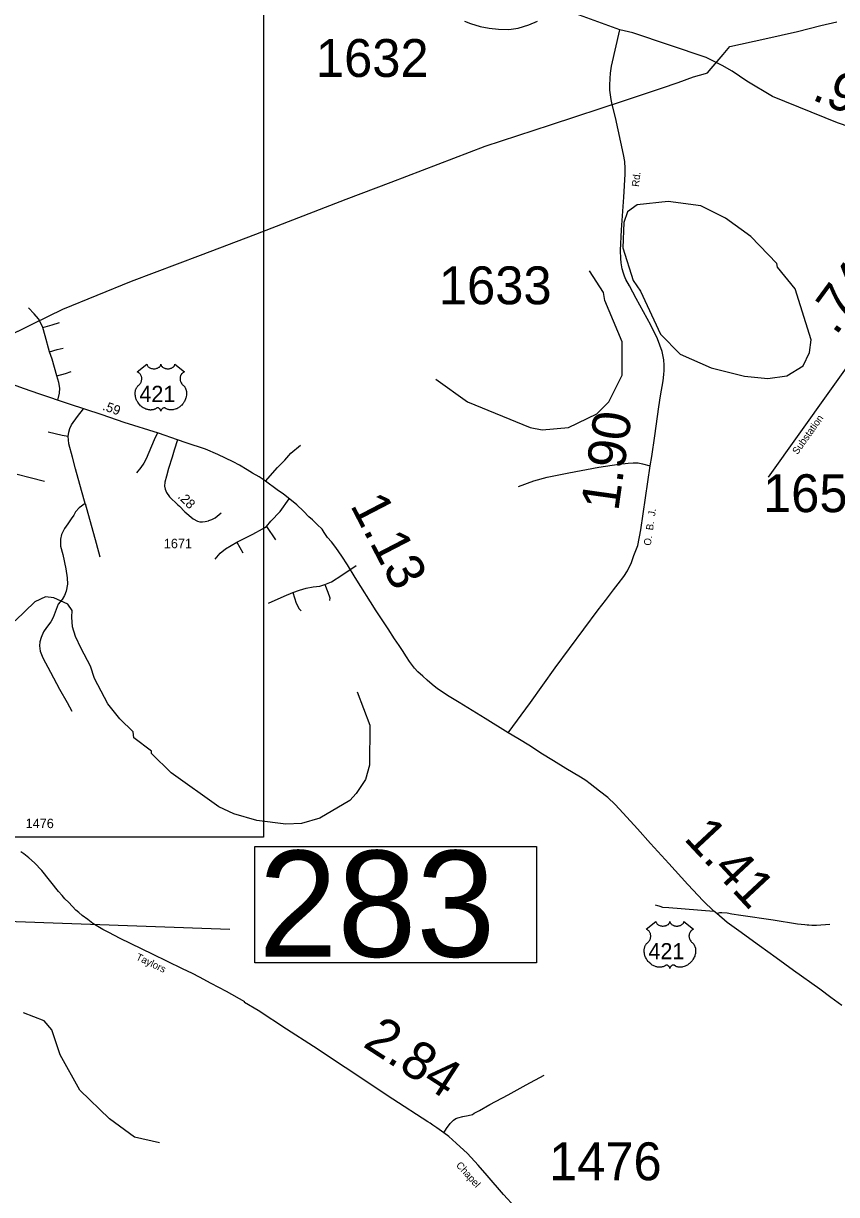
# Model space of a CAD drawing. Extents: x 2093524 to 2270757, y 289120 to 570408.
# Drawn here: x 2138622 to 2149355, y 529637 to 545096 of the extents above; entities that cross this region are included whole.
import ezdxf

# ---------------------------------------------------------------- set-up
doc = ezdxf.new("R2010")
doc.units = 0
for name, color, linetype in [('Exist Hydrographic Creek Single Shore', 7, 'Continuous'), ('Exist Hydrographic Misc Water Feature', 7, 'Continuous'), ('Exist Hydrographic Pond Under 1500 Sq Ft', 7, 'Continuous'), ('Exist Road Non-System Type 51', 7, 'Continuous'), ('Exist Road Primary US Attributed', 7, 'Continuous'), ('Exist Road Primary US Mileage Hundredths English Label', 7, 'Continuous'), ('Exist Road Primary US Shield CELL', 7, 'Continuous'), ('Exist Road Primary US Shield Number Label', 7, 'Continuous'), ('Exist Road Secondary Mileage Hundredths English Label', 7, 'Continuous'), ('Exist Road Secondary Structure Standard Bridge Number Label', 7, 'Continuous'), ('Exist Road Secondary Type 51 Attributed', 7, 'Continuous'), ('Exist Road Secondary Type 51 Label', 7, 'Continuous'), ('Exist Road Secondary Type 51 Number Label', 7, 'Continuous'), ('Exist Utilities Electrical Transmission Line', 7, 'Continuous'), ('Map Preparation Inset Cut Line', 7, 'Continuous')]:
    doc.layers.add(name, color=color, linetype=linetype)

msp = doc.modelspace()

# ---------------------------------------------------------------- linework, layer by layer
at = {"layer": 'Exist Hydrographic Creek Single Shore'}
for points in [[(2143026, 536271), (2143195, 535831), (2143188, 535306), (2143139, 535114), (2143016, 534929), (2142932, 534839), (2142533, 534605), (2142293, 534534), (2142084, 534525), (2141701, 534575), (2141400, 534663), (2141200, 534756), (2140573, 535202), (2140314, 535460), (2140314, 535492), (2140080, 535668), (2140071, 535743), (2139895, 535917), (2139736, 536114), (2139560, 536449), (2139509, 536614), (2139383, 536846), (2139310, 537002), (2139268, 537132), (2139262, 537259), (2139264, 537347), (2139206, 537430), (2139022, 537513), (2138914, 537528), (2138772, 537462), (2138515, 537211)], [(2140420, 530320), (2140086, 530393), (2139760, 530635), (2139367, 531014), (2139107, 531482), (2138997, 531812), (2138896, 531929), (2138621, 532036)]]:
    msp.add_lwpolyline(points, dxfattribs=at)
at = {"layer": 'Exist Hydrographic Misc Water Feature'}
msp.add_lwpolyline([(2144066, 540400), (2144485, 540103), (2145310, 539764), (2145469, 539732), (2145818, 539764), (2146192, 539944), (2146350, 540101), (2146524, 540452), (2146523, 540895), (2146295, 541441), (2146277, 541543), (2146093, 541832)], dxfattribs=at)
at = {"layer": 'Exist Hydrographic Pond Under 1500 Sq Ft'}
msp.add_lwpolyline([(2148449, 540410), (2148699, 540444), (2148914, 540578), (2148996, 540753), (2149020, 540920), (2148809, 541593), (2148576, 541877), (2148566, 541926), (2148223, 542284), (2147889, 542524), (2147564, 542688), (2147131, 542746), (2146722, 542701), (2146597, 542609), (2146549, 542469), (2146533, 542134), (2146669, 541702), (2146768, 541562), (2147029, 540996), (2147289, 540732), (2147699, 540550), (2148140, 540442), (2148449, 540410)], dxfattribs=at)
at = {"layer": 'Exist Road Non-System Type 51'}
for p, q in [((2141831, 538455), (2141948, 538280)), ((2141438, 538248), (2141517, 538110))]:
    msp.add_line(p, q, dxfattribs=at)
for points in [[(2139074, 540123), (2139098, 540215), (2139102, 540282), (2139089, 540355), (2139062, 540445), (2139003, 540663), (2138967, 540762), (2138908, 540971), (2138876, 541084), (2138849, 541147), (2138822, 541197), (2138763, 541265), (2138691, 541342)], [(2138876, 541084), (2139003, 541116), (2139098, 541147)], [(2138967, 540762), (2139066, 540790), (2139148, 540808)], [(2139062, 540445), (2139179, 540477), (2139252, 540500)], [(2139437, 538759), (2139390, 538929), (2139311, 539218), (2139268, 539370), (2139220, 539548), (2139215, 539599), (2139212, 539644), (2139220, 539700), (2139236, 539748), (2139258, 539798), (2139335, 539907), (2139413, 540011)], [(2139212, 539644), (2139133, 539655), (2138949, 539700)], [(2140390, 539691), (2140347, 539601), (2140241, 539349), (2140209, 539290), (2140172, 539234), (2140113, 539165)], [(2141818, 539054), (2141976, 539235), (2142072, 539331), (2142153, 539422), (2142278, 539529)], [(2145156, 538983), (2145358, 539059), (2145533, 539108), (2145820, 539166), (2146215, 539238), (2146480, 539277), (2146602, 539290), (2146668, 539295), (2146734, 539295), (2146792, 539282), (2146894, 539258)], [(2138539, 539148), (2138711, 539101), (2138900, 539053)], [(2141151, 538025), (2141220, 538104), (2141289, 538163), (2141438, 538248), (2141650, 538354), (2141778, 538423), (2141831, 538455), (2141889, 538525), (2142012, 538652), (2142130, 538822)], [(2139437, 538759), (2139359, 538702), (2139308, 538651), (2139285, 538607), (2139254, 538557), (2139207, 538489), (2139163, 538428), (2139126, 538351), (2139113, 538287), (2139113, 538195), (2139140, 538084), (2139182, 537898), (2139199, 537780), (2139202, 537696), (2139185, 537601), (2139165, 537544), (2139135, 537490), (2139081, 537429), (2139054, 537361), (2139013, 537253), (2138983, 537196), (2138925, 537122), (2138885, 537064), (2138854, 536990), (2138839, 536932), (2138836, 536882), (2138843, 536811), (2138880, 536723), (2138978, 536534), (2139096, 536308), (2139197, 536132), (2139261, 536017)], [(2139437, 538759), (2139582, 538236), (2139629, 538057)], [(2141108, 538550), (2141153, 538572), (2141232, 538634)], [(2141858, 537445), (2142065, 537535), (2142176, 537583), (2142267, 537615), (2142352, 537642), (2142447, 537658), (2142533, 537668), (2142602, 537690), (2142687, 537727), (2142825, 537812), (2143016, 537940)], [(2142602, 537690), (2142639, 537589), (2142665, 537514), (2142660, 537477)], [(2142176, 537583), (2142224, 537445), (2142261, 537371), (2142288, 537344)], [(2146961, 533460), (2146991, 533453), (2147007, 533447), (2147021, 533442), (2147058, 533432), (2147140, 533426), (2147733, 533380)], [(2147773, 533349), (2147813, 533360), (2147839, 533362), (2147909, 533355), (2147971, 533343), (2148090, 533327), (2148517, 533262), (2148840, 533212), (2148934, 533202), (2148968, 533199), (2148990, 533197), (2149029, 533194), (2149089, 533193), (2149268, 533205)], [(2144169, 530450), (2144208, 530509), (2144253, 530574), (2144286, 530606), (2144298, 530621), (2144331, 530639), (2144355, 530652), (2144421, 530669), (2144493, 530680), (2144548, 530696), (2144570, 530710), (2144643, 530745), (2144780, 530824), (2145021, 530953), (2145257, 531086), (2145496, 531211)]]:
    msp.add_lwpolyline(points, dxfattribs=at)
at = {"layer": 'Exist Road Primary US Attributed'}
for points in [[(2140656, 539599), (2140404, 539686), (2139950, 539828), (2139662, 539930), (2139215, 540077), (2138837, 540202), (2138625, 540278), (2138395, 540361), (2138135, 540450), (2138000, 540497), (2137696, 540597)], [(2145019, 535734), (2144717, 535920), (2144373, 536133), (2144243, 536210), (2144087, 536313), (2144016, 536368), (2143949, 536428), (2143892, 536479), (2143827, 536538), (2143786, 536587), (2143720, 536672), (2143677, 536737), (2143627, 536818), (2143582, 536883), (2143520, 536972), (2143437, 537106), (2143278, 537343), (2143002, 537781), (2142900, 537949), (2142824, 538066), (2142746, 538180), (2142688, 538255), (2142635, 538312), (2142590, 538377), (2142567, 538421), (2142498, 538481), (2142436, 538542), (2142389, 538585), (2142320, 538658), (2142230, 538742), (2142118, 538832), (2142053, 538884), (2141972, 538939), (2141818, 539054), (2141785, 539075), (2141733, 539112), (2141646, 539160), (2141573, 539205), (2141473, 539264), (2141390, 539309), (2141188, 539404), (2141025, 539476), (2140772, 539559), (2140656, 539599)], [(2149425, 532134), (2149278, 532237), (2149132, 532348), (2148785, 532595), (2148557, 532760), (2148338, 532920), (2148064, 533117), (2147912, 533230), (2147773, 533349), (2147733, 533380), (2147594, 533513), (2147392, 533729), (2147142, 534006), (2146901, 534271), (2146727, 534466), (2146537, 534672), (2146434, 534788), (2146336, 534880), (2146225, 534964), (2146103, 535057), (2146044, 535102), (2145973, 535147), (2145783, 535261), (2145617, 535364), (2145450, 535464), (2145313, 535554), (2145149, 535658), (2145019, 535734)]]:
    msp.add_lwpolyline(points, dxfattribs=at)
at = {"layer": 'Exist Road Primary US Shield CELL'}
for points in [[(2140252, 540599), (2140252, 540594), (2140254, 540588), (2140255, 540585), (2140258, 540578), (2140263, 540571), (2140269, 540564), (2140277, 540557), (2140282, 540554), (2140291, 540549), (2140301, 540545), (2140312, 540542), (2140323, 540540), (2140336, 540538), (2140348, 540538), (2140361, 540539), (2140376, 540542), (2140382, 540544), (2140390, 540546), (2140397, 540549), (2140405, 540553), (2140411, 540557), (2140416, 540561), (2140422, 540567), (2140428, 540574), (2140430, 540578), (2140432, 540581), (2140435, 540589), (2140436, 540593), (2140436, 540600), (2140437, 540594), (2140437, 540590), (2140438, 540586), (2140440, 540582), (2140442, 540577), (2140445, 540572), (2140451, 540566), (2140455, 540562), (2140458, 540560), (2140467, 540554), (2140477, 540549), (2140482, 540546), (2140487, 540544), (2140494, 540543), (2140500, 540541), (2140507, 540540), (2140514, 540539), (2140521, 540538), (2140527, 540538), (2140534, 540538), (2140540, 540539), (2140547, 540539), (2140554, 540541), (2140560, 540542), (2140568, 540544), (2140575, 540546), (2140581, 540549), (2140589, 540553), (2140595, 540557), (2140600, 540561), (2140606, 540566), (2140611, 540572), (2140614, 540577), (2140616, 540581), (2140618, 540586), (2140619, 540592), (2140620, 540596), (2140620, 540600), (2140749, 540497), (2140746, 540496), (2140739, 540493), (2140733, 540490), (2140724, 540483), (2140721, 540480), (2140717, 540476), (2140713, 540473), (2140710, 540469), (2140706, 540464), (2140703, 540459), (2140700, 540453), (2140697, 540448), (2140694, 540438), (2140692, 540431), (2140690, 540426), (2140689, 540414), (2140689, 540409), (2140689, 540403), (2140689, 540398), (2140689, 540392), (2140690, 540386), (2140691, 540381), (2140693, 540375), (2140695, 540368), (2140698, 540361), (2140704, 540350), (2140711, 540339), (2140717, 540332), (2140722, 540327), (2140730, 540320), (2140734, 540316), (2140739, 540311), (2140747, 540302), (2140751, 540298), (2140754, 540293), (2140757, 540288), (2140760, 540282), (2140762, 540277), (2140767, 540266), (2140770, 540256), (2140772, 540250), (2140774, 540237), (2140775, 540231), (2140776, 540219), (2140776, 540204), (2140775, 540190), (2140772, 540173), (2140770, 540163), (2140767, 540152), (2140763, 540142), (2140758, 540127), (2140752, 540117), (2140746, 540104), (2140741, 540097), (2140736, 540089), (2140729, 540079), (2140721, 540069), (2140711, 540059), (2140704, 540051), (2140694, 540042), (2140688, 540037), (2140679, 540031), (2140667, 540023), (2140655, 540016), (2140645, 540011), (2140637, 540007), (2140625, 540003), (2140606, 539998), (2140599, 539996), (2140591, 539995), (2140583, 539994), (2140576, 539994), (2140566, 539994), (2140556, 539995), (2140547, 539996), (2140537, 539998), (2140527, 540001), (2140517, 540005), (2140508, 540009), (2140492, 540019), (2140487, 540022), (2140485, 540022), (2140479, 540023), (2140473, 540022), (2140467, 540019), (2140463, 540017), (2140459, 540014), (2140455, 540011), (2140451, 540007), (2140448, 540004), (2140445, 540001), (2140441, 539994), (2140439, 539990), (2140437, 539986), (2140436, 539980), (2140434, 539988), (2140432, 539993), (2140429, 539998), (2140426, 540002), (2140422, 540007), (2140418, 540011), (2140413, 540015), (2140408, 540018), (2140403, 540020), (2140400, 540021), (2140395, 540023), (2140391, 540023), (2140388, 540023), (2140384, 540022), (2140378, 540018), (2140372, 540014), (2140366, 540010), (2140359, 540006), (2140354, 540004), (2140348, 540001), (2140341, 539999), (2140333, 539997), (2140324, 539995), (2140317, 539994), (2140310, 539994), (2140303, 539993), (2140296, 539993), (2140289, 539994), (2140281, 539995), (2140271, 539996), (2140263, 539998), (2140255, 540000), (2140246, 540003), (2140237, 540006), (2140225, 540012), (2140217, 540016), (2140204, 540023), (2140189, 540033), (2140178, 540043), (2140169, 540050), (2140157, 540063), (2140150, 540071), (2140139, 540085), (2140131, 540096), (2140127, 540104), (2140120, 540116), (2140116, 540124), (2140111, 540135), (2140107, 540146), (2140104, 540156), (2140103, 540162), (2140100, 540173), (2140099, 540181), (2140097, 540192), (2140096, 540203), (2140096, 540213), (2140096, 540222), (2140097, 540232), (2140099, 540243), (2140101, 540252), (2140103, 540259), (2140106, 540267), (2140109, 540275), (2140114, 540284), (2140118, 540291), (2140123, 540299), (2140128, 540305), (2140134, 540312), (2140141, 540319), (2140148, 540324), (2140155, 540331), (2140159, 540336), (2140163, 540342), (2140167, 540347), (2140170, 540353), (2140174, 540360), (2140176, 540366), (2140179, 540374), (2140181, 540380), (2140182, 540388), (2140183, 540396), (2140184, 540405), (2140184, 540412), (2140183, 540421), (2140181, 540430), (2140179, 540437), (2140176, 540446), (2140173, 540452), (2140168, 540460), (2140162, 540468), (2140157, 540475), (2140151, 540480), (2140146, 540485), (2140140, 540488), (2140134, 540492), (2140127, 540495), (2140124, 540497)], [(2146971, 533243), (2146971, 533238), (2146973, 533231), (2146974, 533228), (2146977, 533222), (2146981, 533215), (2146988, 533207), (2146996, 533201), (2147001, 533198), (2147010, 533193), (2147020, 533189), (2147031, 533186), (2147042, 533183), (2147055, 533182), (2147067, 533182), (2147080, 533183), (2147095, 533186), (2147101, 533187), (2147109, 533190), (2147116, 533193), (2147124, 533197), (2147130, 533201), (2147135, 533204), (2147141, 533211), (2147147, 533218), (2147149, 533221), (2147151, 533225), (2147154, 533233), (2147155, 533236), (2147155, 533243), (2147156, 533237), (2147156, 533234), (2147157, 533230), (2147159, 533226), (2147161, 533221), (2147164, 533216), (2147170, 533209), (2147174, 533206), (2147177, 533203), (2147186, 533197), (2147196, 533192), (2147201, 533190), (2147206, 533188), (2147213, 533186), (2147219, 533185), (2147226, 533183), (2147233, 533182), (2147240, 533182), (2147246, 533182), (2147253, 533182), (2147259, 533182), (2147266, 533183), (2147273, 533184), (2147279, 533185), (2147287, 533188), (2147294, 533190), (2147300, 533193), (2147308, 533197), (2147314, 533201), (2147319, 533205), (2147324, 533210), (2147330, 533216), (2147333, 533221), (2147335, 533225), (2147337, 533230), (2147338, 533235), (2147339, 533240), (2147339, 533243), (2147468, 533141), (2147465, 533140), (2147458, 533136), (2147452, 533133), (2147443, 533127), (2147439, 533124), (2147436, 533120), (2147432, 533116), (2147429, 533113), (2147425, 533107), (2147422, 533102), (2147419, 533097), (2147416, 533092), (2147412, 533081), (2147411, 533075), (2147409, 533069), (2147408, 533058), (2147407, 533052), (2147407, 533047), (2147408, 533041), (2147408, 533036), (2147409, 533030), (2147410, 533025), (2147412, 533019), (2147414, 533012), (2147417, 533005), (2147423, 532994), (2147430, 532982), (2147436, 532976), (2147441, 532970), (2147449, 532964), (2147453, 532960), (2147458, 532955), (2147466, 532946), (2147469, 532941), (2147473, 532936), (2147476, 532931), (2147479, 532926), (2147481, 532921), (2147486, 532910), (2147489, 532899), (2147491, 532894), (2147493, 532881), (2147494, 532875), (2147495, 532862), (2147495, 532847), (2147494, 532833), (2147491, 532817), (2147489, 532807), (2147486, 532796), (2147482, 532786), (2147476, 532771), (2147471, 532760), (2147464, 532748), (2147460, 532740), (2147454, 532732), (2147448, 532723), (2147440, 532713), (2147430, 532703), (2147423, 532695), (2147413, 532686), (2147407, 532681), (2147398, 532674), (2147386, 532667), (2147374, 532660), (2147364, 532655), (2147356, 532651), (2147344, 532647), (2147325, 532641), (2147318, 532640), (2147310, 532639), (2147302, 532638), (2147295, 532637), (2147285, 532637), (2147275, 532638), (2147266, 532640), (2147256, 532642), (2147246, 532645), (2147236, 532648), (2147227, 532653), (2147211, 532663), (2147206, 532665), (2147204, 532666), (2147198, 532666), (2147192, 532665), (2147186, 532663), (2147182, 532661), (2147178, 532658), (2147174, 532655), (2147169, 532651), (2147166, 532647), (2147164, 532645), (2147160, 532637), (2147158, 532634), (2147156, 532630), (2147155, 532623), (2147153, 532631), (2147151, 532637), (2147148, 532641), (2147145, 532645), (2147140, 532651), (2147136, 532654), (2147132, 532658), (2147126, 532661), (2147122, 532664), (2147118, 532665), (2147114, 532666), (2147110, 532666), (2147107, 532666), (2147103, 532665), (2147097, 532661), (2147091, 532657), (2147085, 532654), (2147078, 532650), (2147073, 532647), (2147067, 532645), (2147059, 532643), (2147052, 532641), (2147043, 532639), (2147036, 532638), (2147029, 532637), (2147022, 532637), (2147014, 532637), (2147008, 532638), (2147000, 532638), (2146990, 532640), (2146982, 532641), (2146974, 532644), (2146965, 532646), (2146956, 532650), (2146944, 532655), (2146936, 532659), (2146923, 532667), (2146908, 532677), (2146896, 532686), (2146888, 532694), (2146876, 532706), (2146869, 532714), (2146857, 532729), (2146850, 532740), (2146846, 532747), (2146839, 532760), (2146835, 532768), (2146830, 532779), (2146826, 532789), (2146823, 532799), (2146821, 532806), (2146819, 532817), (2146818, 532824), (2146816, 532835), (2146815, 532846), (2146815, 532857), (2146815, 532866), (2146816, 532876), (2146818, 532886), (2146820, 532896), (2146822, 532902), (2146825, 532910), (2146828, 532919), (2146833, 532928), (2146837, 532935), (2146842, 532942), (2146847, 532949), (2146853, 532956), (2146860, 532962), (2146866, 532968), (2146874, 532975), (2146878, 532979), (2146882, 532985), (2146886, 532991), (2146889, 532996), (2146893, 533004), (2146895, 533009), (2146898, 533018), (2146900, 533024), (2146901, 533032), (2146902, 533039), (2146903, 533048), (2146902, 533056), (2146901, 533065), (2146900, 533073), (2146898, 533081), (2146895, 533089), (2146892, 533096), (2146887, 533104), (2146881, 533112), (2146876, 533118), (2146870, 533124), (2146864, 533128), (2146859, 533132), (2146853, 533136), (2146846, 533139), (2146842, 533141)]]:
    msp.add_lwpolyline(points, close=True, dxfattribs=at)
at = {"layer": 'Exist Road Secondary Structure Standard Bridge Number Label'}
msp.add_line((2133308, 533430), (2141347, 533142), dxfattribs=at)
msp.add_lwpolyline([(2141676, 534233), (2145392, 534233), (2145392, 532697), (2141676, 532697)], close=True, dxfattribs=at)
at = {"layer": 'Exist Road Secondary Type 51 Attributed'}
for points in [[(2146495, 545010), (2145914, 545225), (2145791, 545264), (2145715, 545293), (2145665, 545298)], [(2144444, 545125), (2144525, 545095), (2144649, 545057), (2144768, 545032), (2144894, 545020), (2145028, 545017), (2145154, 545035), (2145291, 545076), (2145408, 545127)], [(2145019, 535734), (2145313, 536132), (2145640, 536588), (2146209, 537356), (2146304, 537480), (2146409, 537620), (2146474, 537701), (2146548, 537795), (2146594, 537870), (2146646, 537979), (2146680, 538071), (2146731, 538206), (2146771, 538411), (2146894, 539258), (2146918, 539380), (2146954, 539653), (2147007, 540036), (2147032, 540181), (2147068, 540379), (2147074, 540460), (2147079, 540514), (2147080, 540584), (2147076, 540656), (2147052, 540767), (2146991, 540932), (2146905, 541114), (2146710, 541466), (2146623, 541631), (2146575, 541716), (2146556, 541759), (2146543, 541799), (2146526, 541857), (2146512, 541938), (2146507, 541994), (2146501, 542100), (2146518, 542373), (2146547, 542803), (2146565, 543106), (2146565, 543182), (2146559, 543274), (2146544, 543365), (2146436, 543855), (2146394, 544026), (2146379, 544092), (2146361, 544214), (2146361, 544282), (2146365, 544370), (2146370, 544440), (2146386, 544532), (2146495, 545010)], [(2151176, 543044), (2150858, 543039), (2150744, 543060), (2150678, 543091), (2149905, 543543), (2149665, 543665), (2149445, 543756), (2149367, 543782), (2148510, 544133), (2148172, 544332), (2147978, 544466), (2147846, 544540), (2147632, 544645), (2146665, 544970), (2146495, 545010)], [(2151087, 541783), (2150963, 541772), (2150760, 541738), (2150624, 541709), (2150532, 541680), (2150452, 541649), (2150379, 541604), (2150281, 541545), (2150216, 541494), (2150156, 541440), (2150075, 541347), (2149953, 541202), (2149665, 540809), (2148451, 539106)], [(2140656, 539599), (2140613, 539465), (2140585, 539370), (2140538, 539221), (2140511, 539118), (2140487, 539040), (2140484, 538990), (2140491, 538948), (2140512, 538904), (2140549, 538847), (2140658, 538740), (2140680, 538725), (2140754, 538651), (2140862, 538556), (2140921, 538524), (2140949, 538519), (2140986, 538518), (2141020, 538521), (2141063, 538530), (2141070, 538533), (2141108, 538550)], [(2145111, 529471), (2144958, 529640), (2144743, 529887), (2144622, 530023), (2144483, 530178), (2144334, 530315), (2144238, 530405), (2144169, 530450), (2144080, 530520), (2144027, 530555), (2143991, 530580), (2143960, 530596), (2143496, 530898), (2142868, 531314), (2142450, 531593), (2142095, 531822), (2141722, 532067), (2141538, 532173), (2141544, 532181), (2141301, 532316), (2141101, 532422), (2140948, 532507), (2140853, 532553), (2140721, 532617), (2140327, 532811), (2139897, 533018), (2139748, 533095), (2139671, 533134), (2139628, 533161), (2139539, 533217), (2139472, 533268), (2139395, 533322), (2139352, 533361), (2139314, 533393), (2139220, 533491), (2139169, 533542), (2139134, 533585), (2139087, 533638), (2138865, 533916), (2138767, 534018), (2138692, 534082), (2138627, 534135), (2138586, 534162)]]:
    msp.add_lwpolyline(points, dxfattribs=at)
at = {"layer": 'Exist Utilities Electrical Transmission Line'}
msp.add_lwpolyline([(2138345, 540934), (2138753, 541136), (2139143, 541326), (2140047, 541694), (2140961, 542038), (2141689, 542316), (2142881, 542776), (2143475, 543002), (2144717, 543477), (2145579, 543757), (2146571, 544085), (2147045, 544243), (2147263, 544315), (2147468, 544391), (2147623, 544435), (2147653, 544445), (2147700, 544501), (2147856, 544685), (2147946, 544791), (2148406, 544895), (2148838, 544991), (2149148, 545069), (2149360, 545116)], dxfattribs=at)
at = {"layer": 'Map Preparation Inset Cut Line'}
msp.add_lwpolyline([(2141792, 534353), (2122831, 534353), (2122831, 549699), (2141792, 549699)], close=True, dxfattribs=at)

# ---------------------------------------------------------------- texts
at = {"layer": 'Exist Road Primary US Mileage Hundredths English Label'}
for s, height, rotation, p in [('.59', 125, 340.5445, (2139657, 539998)), ('1.13', 500, 297.4336, (2142929, 538737)), ('1.41', 500, 313.0251, (2147326, 534331))]:
    msp.add_text(s, height=height, rotation=rotation, dxfattribs=at).set_placement(p)
at = {"layer": 'Exist Road Primary US Shield Number Label'}
for p in [(2140153, 540100), (2146872, 532744)]:
    msp.add_text('421', height=212.5, dxfattribs=at).set_placement(p)
at = {"layer": 'Exist Road Secondary Mileage Hundredths English Label'}
for s, height, rotation, p in [('.97', 500, 337.6953, (2149014, 544096)), ('.74', 500, 53.743, (2149346, 540966)), ('1.90', 500, 82.0165, (2146473, 538649)), ('.28', 125, 314.9836, (2140651, 538842)), ('2.84', 500, 327.0055, (2143088, 531600))]:
    msp.add_text(s, height=height, rotation=rotation, dxfattribs=at).set_placement(p)
at = {"layer": 'Exist Road Secondary Structure Standard Bridge Number Label'}
msp.add_text('283', height=1400, dxfattribs=at).set_placement((2141726, 532776))
at = {"layer": 'Exist Road Secondary Type 51 Label'}
for s, rotation, p in [('Rd.', 83.1991, (2146745, 542936)), ('Substation', 54.562, (2148839, 539398)), ('O.  B.  J.', 81.7413, (2146902, 538198)), ('Taylors', 334.3162, (2140099, 532742)), ('Chapel', 311.9014, (2144326, 530019))]:
    msp.add_text(s, height=95, rotation=rotation, dxfattribs=at).set_placement(p)
at = {"layer": 'Exist Road Secondary Type 51 Number Label'}
for s, height, p in [('1632', 500, (2142483, 544390)), ('1633', 500, (2144106, 541389)), ('1656', 500, (2148384, 538645)), ('1671', 125, (2140475, 538169)), ('1476', 125, (2138651, 534474)), ('1476', 500, (2145559, 529826))]:
    msp.add_text(s, height=height, dxfattribs=at).set_placement(p)

doc.saveas('drawing.dxf')
